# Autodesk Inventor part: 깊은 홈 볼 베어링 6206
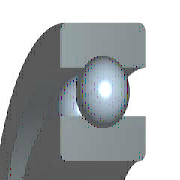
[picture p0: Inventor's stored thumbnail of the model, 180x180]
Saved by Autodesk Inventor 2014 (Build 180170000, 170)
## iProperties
IsCustomPart: 1
Created: 2012-02
Part Number: 깊은 홈 볼 베어링 6206
Material: 강철, 연강
Description: 깊은 그루부 볼 베어링
Document SubType Name: Modeling
Standard: JIS B 1521
Designer: mdu-01
Standards Organization: JIS
Language: ko-KR
Size Designation: 6206 30x62x16
Categories: <MemberInstance><Categories><Category DisplayName="샤프트 부품" InternalName="7f7aeb1f-a693-4053-b835-cee3144e0d98" Mnemonic="SHFT"><Category DisplayName="베어링" Inter
Density: 7.86 g/cm^3
Appearance: 강철(1)
Mass: 175.236 g
Surface Area: 142.005 cm^2
Volume: 22.2946 cm^3
Author: mdu-01
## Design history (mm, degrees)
sketch "스케치" dims "d0" = 8.32 (= -0.26 x WD + 0.26 x BD)
  geometry: L1 (3.84, 23)-(12.16, 23); L2 (8, 23)-(8, 18.84); L3 (8, 23)-(8, 27.16); L4 (4.909, 20.216)-(0, 20.216); L5 (0, 15)-(16, 15); L6 (4.909, 25.784)-(0, 25.784); L7 (0, 31)-(16, 31); L8 (16, 15)-(16, 20.216); L9 (11.091, 20.216)-(16, 20.216); L10 (11.091, 25.784)-(16, 25.784); L11 (16, 31)-(16, 25.784); L12 (-1.4, 0)-(8.4, 0) reference; L13 (0, -0.3)-(0, 5.3) reference
  constraints: 22 end point, 4 point on line, 2 collinear, 2 perpendicular, 2 symmetric about line, 1 midpoint, 1 parallel, 14 other
  dimensions: "d9" = 30 diameter of L5 L12 (= WD); "d11" = 62 diameter of L7 L12 (= BD); "d12" = 16 distance between parallel lines of L8 L13 (= KB); "d13" = 40.432 diameter of L9 L12 (= 0.326 x BD + 0.674 x WD)
revolve "본체" stored, may be unused: angle "d6" = 90 deg
revolve "볼" stored, may be unused: angle "d7" = 90 deg
pattern_circular "IDS_ARRAYBALL[SIMPL:T]" dims angle "d3" = 360 deg
body "Solid1"
fillet "모깎기1" dims "d1" = 1 (= KRS)
other parameters: "WD" = 30 [user parameter; used in 5 equation terms], "BD" = 62 [user parameter; used in 5 equation terms], "KB" = 16 [user parameter; used in 1 equation term], "KRS" = 1 [user parameter; used in 1 equation term], "d4" = 0, "d5" = 0, "d8" = 0, "d14" = 0, "d15" = 0, "BBA" = 0 [user parameter], "BC0" = 1.12e+07 [user parameter], "BC" = 1.95e+07 [user parameter], "BR" = 31 (= 0.5 x BD) [user parameter], "WR" = 15 (= 0.5 x WD) [user parameter]
